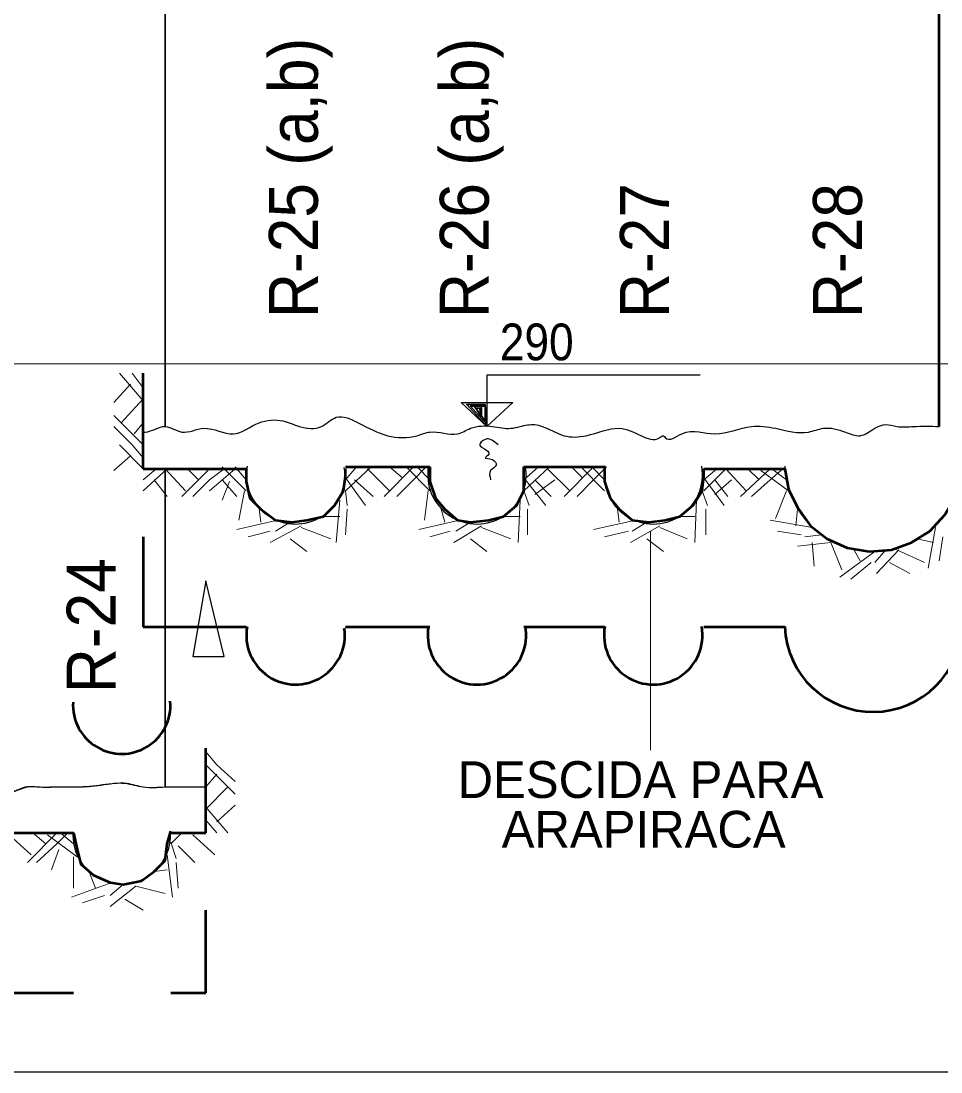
# Model space of a CAD drawing. Extents: x 8426.2 to 8495.4, y 19933.5 to 19963.2.
# Drawn here: x 8473.14 to 8478.14, y 19944.82 to 19950.53 of the extents above; entities that cross this region are included whole.
import ezdxf

# ---------------------------------------------------------------- set-up
doc = ezdxf.new("R2010")
doc.units = 0
doc.header["$LTSCALE"] = 0.11
for name, color, linetype, lineweight in [('1', 7, 'Continuous', 35), ('2', 7, 'Continuous', 13), ('3', 7, 'Continuous', 25), ('4', 7, 'Continuous', 25)]:
    doc.layers.add(name, color=color, linetype=linetype, lineweight=lineweight)

msp = doc.modelspace()

# ---------------------------------------------------------------- linework, layer by layer
at = {"layer": '1'}
msp.add_line((8473.92, 19948.33), (8473.92, 19955.82), dxfattribs=at)
at = {"layer": '1', "lineweight": 25}
msp.add_lwpolyline([(8476.83, 19948.61), (8475.67, 19948.61), (8475.67, 19948.33), (8475.53, 19948.46), (8475.81, 19948.46), (8475.67, 19948.33)], dxfattribs=at)
at = {"layer": '1'}
for points in [[(8475.67, 19948.33), (8475.56, 19948.45), (8475.66, 19948.45), (8475.67, 19948.34), (8475.58, 19948.44), (8475.66, 19948.44), (8475.66, 19948.36), (8475.6, 19948.44), (8475.64, 19948.44), (8475.64, 19948.39), (8475.63, 19948.43)], [(8475.64, 19948.4), (8475.64, 19948.43), (8475.61, 19948.43), (8475.64, 19948.38)], [(8473.92, 19946.37), (8473.92, 19947.42), (8473.92, 19948.1)]]:
    msp.add_lwpolyline(points, dxfattribs=at)
at = {"layer": '1', "lineweight": 25}
msp.add_spline([(8475.73, 19948.23), (8475.66, 19948.26), (8475.63, 19948.23), (8475.67, 19948.2), (8475.68, 19948.18), (8475.66, 19948.16), (8475.7, 19948.15), (8475.72, 19948.12), (8475.69, 19948.09), (8475.69, 19948.04)], degree=3, dxfattribs=at)
at = {"layer": '2', "lineweight": 53}
for p, q in [((8478.13, 19948.33), (8478.13, 19954.72)), ((8473.8, 19948.1), (8473.8, 19948.62)), ((8473.8, 19948.1), (8474.36, 19948.1)), ((8474.9, 19948.11), (8475.36, 19948.11)), ((8475.87, 19948.11), (8476.31, 19948.11)), ((8476.85, 19948.1), (8477.29, 19948.1)), ((8473.8, 19947.73), (8473.8, 19947.24)), ((8473.8, 19947.24), (8474.36, 19947.24)), ((8474.9, 19947.24), (8475.36, 19947.24)), ((8475.87, 19947.24), (8476.31, 19947.24)), ((8476.85, 19947.24), (8477.29, 19947.24)), ((8474.14, 19946.12), (8474.14, 19946.58)), ((8472.95, 19946.12), (8473.42, 19946.12)), ((8473.95, 19946.12), (8474.14, 19946.12)), ((8474.14, 19945.25), (8474.14, 19945.7)), ((8472.95, 19945.25), (8473.42, 19945.25)), ((8473.95, 19945.25), (8474.14, 19945.25))]:
    msp.add_line(p, q, dxfattribs=at)
at = {"layer": '2'}
for p, q in [((8473.8, 19948.47), (8473.67, 19948.62)), ((8473.8, 19948.54), (8473.74, 19948.62)), ((8473.73, 19948.56), (8473.64, 19948.46)), ((8473.8, 19948.48), (8473.68, 19948.35)), ((8473.8, 19948.23), (8473.64, 19948.39)), ((8473.74, 19948.23), (8473.64, 19948.33)), ((8473.8, 19948.35), (8473.75, 19948.29)), ((8473.8, 19948.1), (8473.67, 19948.23)), ((8473.8, 19948.16), (8473.74, 19948.23)), ((8473.73, 19948.17), (8473.64, 19948.09)), ((8473.87, 19948.1), (8473.8, 19948.04)), ((8473.93, 19948.1), (8473.8, 19947.98)), ((8473.92, 19948.1), (8474.03, 19947.98)), ((8474.16, 19948.1), (8474.01, 19947.95)), ((8474.04, 19948.1), (8474.1, 19948.04)), ((8474.24, 19948.1), (8474.16, 19948.04)), ((8474.3, 19948.1), (8474.16, 19947.98)), ((8474.36, 19947.98), (8474.23, 19948.11)), ((8474.36, 19948.04), (8474.3, 19948.11)), ((8474.96, 19948.11), (8474.9, 19948.04)), ((8475.04, 19948.11), (8474.9, 19947.98)), ((8475.02, 19948.1), (8475.14, 19947.98)), ((8475.27, 19948.11), (8475.11, 19947.95)), ((8475.14, 19948.11), (8475.21, 19948.05)), ((8475.36, 19947.98), (8475.23, 19948.11)), ((8475.34, 19948.11), (8475.27, 19948.04)), ((8475.36, 19948.04), (8475.29, 19948.11)), ((8475.95, 19948.11), (8475.87, 19948.04)), ((8476.01, 19948.11), (8475.87, 19947.98)), ((8476, 19948.1), (8476.12, 19947.98)), ((8476.25, 19948.11), (8476.09, 19947.95)), ((8476.13, 19948.11), (8476.19, 19948.05)), ((8476.31, 19947.98), (8476.18, 19948.11)), ((8476.31, 19948.04), (8476.24, 19948.11)), ((8476.32, 19948.11), (8476.25, 19948.04)), ((8476.92, 19948.1), (8476.85, 19948.04)), ((8476.97, 19948.1), (8476.85, 19947.98)), ((8476.97, 19948.1), (8477.08, 19947.98)), ((8477.21, 19948.1), (8477.05, 19947.95)), ((8477.09, 19948.1), (8477.15, 19948.04)), ((8477.31, 19947.98), (8477.16, 19948.09)), ((8477.28, 19948.1), (8477.21, 19948.04)), ((8477.3, 19948.04), (8477.22, 19948.1)), ((8473.86, 19948.04), (8473.93, 19947.95)), ((8474.16, 19948.04), (8474.07, 19947.95)), ((8474.23, 19948.04), (8474.31, 19947.95)), ((8474.27, 19948.03), (8474.23, 19947.93)), ((8474.9, 19948.05), (8475.01, 19947.9)), ((8474.95, 19948.04), (8475.05, 19947.95)), ((8475.27, 19948.04), (8475.18, 19947.95)), ((8475.87, 19948.05), (8475.99, 19947.9)), ((8475.93, 19948.04), (8476.02, 19947.95)), ((8475.93, 19947.96), (8476.04, 19948.04)), ((8476.25, 19948.04), (8476.16, 19947.95)), ((8476.85, 19948.05), (8476.96, 19947.9)), ((8476.91, 19948.04), (8476.98, 19947.95)), ((8476.91, 19947.96), (8477, 19948.04)), ((8477.21, 19948.04), (8477.11, 19947.95)), ((8474.35, 19947.98), (8474.32, 19947.82)), ((8474.9, 19947.98), (8474.91, 19947.9)), ((8475.35, 19947.98), (8475.33, 19947.82)), ((8475.87, 19947.98), (8475.9, 19947.9)), ((8476.84, 19947.98), (8476.87, 19947.9)), ((8477.3, 19947.98), (8477.24, 19947.83)), ((8474.87, 19947.93), (8474.85, 19947.7)), ((8475.85, 19947.93), (8475.84, 19947.7)), ((8476.81, 19947.93), (8476.8, 19947.7)), ((8474.43, 19947.88), (8474.44, 19947.81)), ((8474.91, 19947.88), (8474.9, 19947.74)), ((8475.42, 19947.88), (8475.44, 19947.81)), ((8475.89, 19947.88), (8475.89, 19947.74)), ((8476.38, 19947.88), (8476.39, 19947.81)), ((8476.86, 19947.88), (8476.86, 19947.74)), ((8477.36, 19947.88), (8477.35, 19947.79)), ((8474.53, 19947.82), (8474.31, 19947.77)), ((8474.6, 19947.81), (8474.52, 19947.76)), ((8474.78, 19947.84), (8474.87, 19947.84)), ((8475.52, 19947.82), (8475.3, 19947.77)), ((8475.58, 19947.81), (8475.5, 19947.76)), ((8475.76, 19947.84), (8475.85, 19947.84)), ((8476.48, 19947.82), (8476.25, 19947.77)), ((8476.54, 19947.81), (8476.46, 19947.76)), ((8476.72, 19947.84), (8476.8, 19947.84)), ((8477.44, 19947.78), (8477.21, 19947.82)), ((8474.49, 19947.76), (8474.37, 19947.73)), ((8474.66, 19947.79), (8474.49, 19947.7)), ((8474.66, 19947.78), (8474.82, 19947.72)), ((8475.47, 19947.76), (8475.36, 19947.73)), ((8475.64, 19947.79), (8475.49, 19947.7)), ((8475.64, 19947.78), (8475.8, 19947.72)), ((8476.44, 19947.76), (8476.31, 19947.73)), ((8476.61, 19947.79), (8476.45, 19947.7)), ((8476.61, 19947.78), (8476.76, 19947.72)), ((8477.38, 19947.74), (8477.25, 19947.76)), ((8478.11, 19947.78), (8478.07, 19947.56)), ((8474.6, 19947.72), (8474.69, 19947.65)), ((8475.58, 19947.72), (8475.67, 19947.65)), ((8476.54, 19947.72), (8476.63, 19947.65)), ((8477.54, 19947.7), (8477.36, 19947.68)), ((8477.49, 19947.74), (8477.4, 19947.73)), ((8477.44, 19947.7), (8477.45, 19947.57)), ((8477.54, 19947.7), (8477.6, 19947.55)), ((8478.01, 19947.72), (8478.1, 19947.7)), ((8478.15, 19947.73), (8478.13, 19947.6)), ((8477.78, 19947.65), (8477.59, 19947.51)), ((8477.66, 19947.67), (8477.7, 19947.6)), ((8477.84, 19947.66), (8477.78, 19947.59)), ((8477.91, 19947.66), (8477.79, 19947.53)), ((8477.9, 19947.66), (8478.05, 19947.59)), ((8477.76, 19947.59), (8477.65, 19947.5)), ((8477.86, 19947.59), (8477.97, 19947.53)), ((8474.14, 19946.56), (8474.2, 19946.49)), ((8474.14, 19946.49), (8474.3, 19946.33)), ((8474.2, 19946.49), (8474.3, 19946.4)), ((8474.14, 19946.37), (8474.2, 19946.44)), ((8474.14, 19946.25), (8474.26, 19946.37)), ((8474.14, 19946.26), (8474.26, 19946.12)), ((8474.2, 19946.18), (8474.3, 19946.27)), ((8474.14, 19946.19), (8474.2, 19946.12)), ((8473.07, 19946.11), (8473.19, 19946)), ((8473.33, 19946.12), (8473.17, 19945.96)), ((8473.2, 19946.12), (8473.27, 19946.06)), ((8473.44, 19945.99), (8473.28, 19946.11)), ((8473.39, 19946.12), (8473.33, 19946.06)), ((8473.42, 19946.06), (8473.35, 19946.12)), ((8474.01, 19946.12), (8473.95, 19946.06)), ((8474.07, 19946.11), (8474.19, 19946)), ((8473.33, 19946.06), (8473.22, 19945.96)), ((8473.34, 19946.03), (8473.3, 19945.92)), ((8473.95, 19946.07), (8473.98, 19945.98)), ((8473.99, 19946.05), (8474.08, 19945.96)), ((8473.42, 19945.99), (8473.42, 19945.82)), ((8473.93, 19946), (8473.96, 19945.77)), ((8473.86, 19945.91), (8473.93, 19945.92)), ((8473.98, 19945.96), (8473.99, 19945.82)), ((8473.51, 19945.9), (8473.54, 19945.82)), ((8473.63, 19945.85), (8473.41, 19945.77)), ((8473.69, 19945.84), (8473.62, 19945.78)), ((8473.76, 19945.83), (8473.62, 19945.72)), ((8473.76, 19945.83), (8473.92, 19945.79)), ((8473.59, 19945.78), (8473.47, 19945.74)), ((8473.7, 19945.76), (8473.8, 19945.7))]:
    msp.add_line(p, q, dxfattribs=at)
at = {"layer": '2', "lineweight": 35}
msp.add_line((8473.8, 19948.62), (8473.8, 19948.1), dxfattribs=at)
at = {"layer": '2', "lineweight": 25}
msp.add_line((8474.14, 19946.12), (8474.14, 19946.58), dxfattribs=at)
at = {"layer": '2', "lineweight": 53}
for points in [[(8474.36, 19948.1), (8474.36, 19948.03), (8474.38, 19947.94), (8474.44, 19947.88), (8474.52, 19947.82), (8474.61, 19947.81), (8474.69, 19947.82), (8474.78, 19947.84), (8474.84, 19947.9), (8474.89, 19947.98), (8474.9, 19948.06), (8474.9, 19948.1)], [(8475.36, 19948.11), (8475.36, 19948.03), (8475.39, 19947.94), (8475.44, 19947.88), (8475.51, 19947.82), (8475.58, 19947.81), (8475.68, 19947.82), (8475.76, 19947.84), (8475.83, 19947.9), (8475.87, 19947.98), (8475.87, 19948.06), (8475.87, 19948.11)], [(8476.31, 19948.11), (8476.31, 19948.03), (8476.34, 19947.94), (8476.39, 19947.88), (8476.46, 19947.82), (8476.55, 19947.81), (8476.64, 19947.82), (8476.72, 19947.84), (8476.79, 19947.9), (8476.84, 19947.98), (8476.85, 19948.06), (8476.85, 19948.1)], [(8477.29, 19948.1), (8477.31, 19947.99), (8477.36, 19947.89), (8477.43, 19947.79), (8477.52, 19947.72), (8477.63, 19947.67), (8477.75, 19947.65), (8477.87, 19947.66), (8477.98, 19947.7), (8478.08, 19947.76), (8478.16, 19947.85), (8478.22, 19947.95), (8478.25, 19948.06), (8478.25, 19948.11)], [(8473.42, 19946.12), (8473.44, 19946.03), (8473.46, 19945.95), (8473.53, 19945.89), (8473.62, 19945.85), (8473.69, 19945.84), (8473.79, 19945.86), (8473.86, 19945.91), (8473.92, 19945.97), (8473.93, 19946.06), (8473.95, 19946.13)]]:
    msp.add_lwpolyline(points, dxfattribs=at)
at = {"layer": '2', "lineweight": 25}
msp.add_lwpolyline([(8474.14, 19947.49), (8474.07, 19947.08), (8474.24, 19947.08)], close=True, dxfattribs=at)
at = {"layer": '2', "lineweight": 53}
for centre, radius, start, end in [((8474.6288, 19947.1949), 0.268, 169.8463, 8.4206), ((8475.6155, 19947.1949), 0.268, 169.5566, 10.4434), ((8476.5748, 19947.1949), 0.268, 169.5566, 10.1537), ((8477.7712, 19947.2595), 0.4815, 182.0654, 359.0456), ((8473.6828, 19946.815), 0.2652, 176.5407, 4.4698), ((8473.6828, 19946.815), 0.2652, 176.5407, 4.4698), ((8473.6828, 19946.815), 0.2652, 176.5407, 4.4698)]:
    msp.add_arc(centre, radius, start, end, dxfattribs=at)
at = {"layer": '3', "lineweight": 13}
msp.add_line((8431.27, 19948.67), (8493.73, 19948.67), dxfattribs=at)
at = {"layer": '3'}
for p, q in [((8475.36, 19948.11), (8474.9, 19948.11)), ((8476.31, 19948.11), (8475.87, 19948.11)), ((8477.29, 19948.1), (8476.85, 19948.1)), ((8473.42, 19946.12), (8472.95, 19946.12)), ((8474.14, 19946.12), (8473.95, 19946.12)), ((8431.27, 19944.82), (8493.73, 19944.82))]:
    msp.add_line(p, q, dxfattribs=at)
msp.add_lwpolyline([(8474.36, 19948.1), (8473.8, 19948.1), (8473.8, 19948.3)], dxfattribs=at)
for centre, radius, start, end in [((8474.6288, 19948.0676), 0.268, 169.8463, 8.4206), ((8475.6155, 19948.0676), 0.268, 169.5566, 10.4434), ((8476.5748, 19948.0676), 0.268, 169.5566, 10.1537), ((8477.7712, 19948.1322), 0.4815, 182.0654, 359.0456), ((8473.6828, 19946.1068), 0.2652, 176.5407, 4.4698)]:
    msp.add_arc(centre, radius, start, end, dxfattribs=at)
for points in [[(8473.8, 19948.3), (8473.81, 19948.3), (8473.92, 19948.33), (8474.01, 19948.3), (8474.13, 19948.32), (8474.29, 19948.29), (8474.43, 19948.35), (8474.56, 19948.36), (8474.65, 19948.33), (8474.77, 19948.33), (8474.85, 19948.38), (8474.97, 19948.35), (8475.13, 19948.28), (8475.29, 19948.28), (8475.36, 19948.3), (8475.51, 19948.29), (8475.58, 19948.32), (8475.7, 19948.33), (8475.8, 19948.32), (8475.85, 19948.33), (8475.93, 19948.34), (8476.09, 19948.28), (8476.21, 19948.28), (8476.39, 19948.32), (8476.51, 19948.28), (8476.61, 19948.27), (8476.63, 19948.28), (8476.64, 19948.27), (8476.73, 19948.29), (8476.91, 19948.29), (8477.11, 19948.33), (8477.24, 19948.32), (8477.42, 19948.3), (8477.5, 19948.32), (8477.62, 19948.3), (8477.7, 19948.28), (8477.78, 19948.32), (8477.84, 19948.34), (8477.9, 19948.33), (8477.99, 19948.33), (8478.13, 19948.33)], [(8473.8, 19948.3), (8473.81, 19948.3), (8473.92, 19948.33), (8474.01, 19948.3), (8474.13, 19948.32), (8474.29, 19948.29), (8474.43, 19948.35), (8474.56, 19948.36), (8474.65, 19948.33), (8474.77, 19948.33), (8474.85, 19948.38), (8474.97, 19948.35), (8475.13, 19948.28), (8475.29, 19948.28), (8475.36, 19948.3), (8475.51, 19948.29), (8475.58, 19948.32), (8475.7, 19948.33), (8475.8, 19948.32), (8475.85, 19948.33), (8475.93, 19948.34), (8476.09, 19948.28), (8476.21, 19948.28), (8476.39, 19948.32), (8476.51, 19948.28), (8476.61, 19948.27), (8476.63, 19948.28), (8476.64, 19948.27), (8476.73, 19948.29), (8476.91, 19948.29), (8477.11, 19948.33), (8477.24, 19948.32), (8477.42, 19948.3), (8477.5, 19948.32), (8477.62, 19948.3), (8477.7, 19948.28), (8477.78, 19948.32), (8477.84, 19948.34), (8477.9, 19948.33), (8477.99, 19948.33), (8478.13, 19948.33)], [(8473.8, 19948.3), (8473.81, 19948.3), (8473.92, 19948.33), (8474.01, 19948.3), (8474.13, 19948.32), (8474.29, 19948.29), (8474.43, 19948.35), (8474.56, 19948.36), (8474.65, 19948.33), (8474.77, 19948.33), (8474.85, 19948.38), (8474.97, 19948.35), (8475.13, 19948.28), (8475.29, 19948.28), (8475.36, 19948.3), (8475.51, 19948.29), (8475.58, 19948.32), (8475.7, 19948.33), (8475.8, 19948.32), (8475.85, 19948.33), (8475.93, 19948.34), (8476.09, 19948.28), (8476.21, 19948.28), (8476.39, 19948.32), (8476.51, 19948.28), (8476.61, 19948.27), (8476.63, 19948.28), (8476.64, 19948.27), (8476.73, 19948.29), (8476.91, 19948.29), (8477.11, 19948.33), (8477.24, 19948.32), (8477.42, 19948.3), (8477.5, 19948.32), (8477.62, 19948.3), (8477.7, 19948.28), (8477.78, 19948.32), (8477.84, 19948.34), (8477.9, 19948.33), (8477.99, 19948.33), (8478.13, 19948.33)], [(8473.8, 19948.3), (8473.81, 19948.3), (8473.92, 19948.33), (8474.01, 19948.3), (8474.13, 19948.32), (8474.29, 19948.29), (8474.43, 19948.35), (8474.56, 19948.36), (8474.65, 19948.33), (8474.77, 19948.33), (8474.85, 19948.38), (8474.97, 19948.35), (8475.13, 19948.28), (8475.29, 19948.28), (8475.36, 19948.3), (8475.51, 19948.29), (8475.58, 19948.32), (8475.7, 19948.33), (8475.8, 19948.32), (8475.85, 19948.33), (8475.93, 19948.34), (8476.09, 19948.28), (8476.21, 19948.28), (8476.39, 19948.32), (8476.51, 19948.28), (8476.61, 19948.27), (8476.63, 19948.28), (8476.64, 19948.27), (8476.73, 19948.29), (8476.91, 19948.29), (8477.11, 19948.33), (8477.24, 19948.32), (8477.42, 19948.3), (8477.5, 19948.32), (8477.62, 19948.3), (8477.7, 19948.28), (8477.78, 19948.32), (8477.84, 19948.34), (8477.9, 19948.33), (8477.99, 19948.33), (8478.13, 19948.33)], [(8466.81, 19946.36), (8466.93, 19946.35), (8467.1, 19946.31), (8467.24, 19946.34), (8467.4, 19946.31), (8467.52, 19946.36), (8467.62, 19946.38), (8467.69, 19946.35), (8467.86, 19946.39), (8467.92, 19946.36), (8468.03, 19946.35), (8468.19, 19946.36), (8468.31, 19946.34), (8468.44, 19946.36), (8468.56, 19946.35), (8468.65, 19946.38), (8468.94, 19946.37), (8469.06, 19946.37), (8469.22, 19946.36), (8469.3, 19946.37), (8469.41, 19946.38), (8469.47, 19946.36), (8469.61, 19946.38), (8469.71, 19946.37), (8469.79, 19946.35), (8469.91, 19946.38), (8469.98, 19946.39), (8470.08, 19946.4), (8470.13, 19946.38), (8470.32, 19946.4), (8470.43, 19946.34), (8470.53, 19946.37), (8470.6, 19946.38), (8470.69, 19946.37), (8470.85, 19946.35), (8470.99, 19946.37), (8471.08, 19946.37), (8471.16, 19946.34), (8471.49, 19946.35), (8471.55, 19946.36), (8471.68, 19946.37), (8471.84, 19946.39), (8471.96, 19946.35), (8472.08, 19946.38), (8472.25, 19946.36), (8472.36, 19946.39), (8472.44, 19946.4), (8472.64, 19946.39), (8472.73, 19946.36), (8472.88, 19946.35), (8472.99, 19946.35), (8473.07, 19946.34), (8473.17, 19946.37), (8473.24, 19946.37), (8473.33, 19946.37), (8473.44, 19946.37), (8473.57, 19946.38), (8473.71, 19946.39), (8473.8, 19946.37), (8473.92, 19946.37), (8474.03, 19946.37), (8474.1, 19946.37), (8474.14, 19946.37)], [(8466.81, 19946.36), (8466.91, 19946.35), (8467.1, 19946.31), (8467.24, 19946.34), (8467.4, 19946.31), (8467.52, 19946.36), (8467.6, 19946.38), (8467.69, 19946.35), (8467.85, 19946.39), (8467.91, 19946.36), (8468.03, 19946.35), (8468.18, 19946.36), (8468.3, 19946.34), (8468.43, 19946.36), (8468.56, 19946.35), (8468.65, 19946.38), (8468.93, 19946.37), (8469.06, 19946.37), (8469.2, 19946.36), (8469.29, 19946.37), (8469.4, 19946.38), (8469.47, 19946.36), (8469.61, 19946.38), (8469.7, 19946.37), (8469.78, 19946.35), (8469.91, 19946.38), (8469.97, 19946.39), (8470.07, 19946.4), (8470.13, 19946.38), (8470.31, 19946.4), (8470.42, 19946.34), (8470.53, 19946.37), (8470.59, 19946.38), (8470.68, 19946.37), (8470.84, 19946.35), (8470.98, 19946.37), (8471.07, 19946.37), (8471.15, 19946.34), (8471.48, 19946.35), (8471.54, 19946.36), (8471.67, 19946.37), (8471.84, 19946.39), (8471.96, 19946.35), (8472.08, 19946.38), (8472.25, 19946.36), (8472.34, 19946.39), (8472.44, 19946.4), (8472.64, 19946.39), (8472.72, 19946.36), (8472.88, 19946.35), (8472.99, 19946.35), (8473.07, 19946.34), (8473.16, 19946.37), (8473.24, 19946.37), (8473.31, 19946.37), (8473.42, 19946.37), (8473.56, 19946.38), (8473.7, 19946.39), (8473.8, 19946.37), (8473.92, 19946.37), (8474.03, 19946.37), (8474.1, 19946.37), (8474.13, 19946.37)]]:
    msp.add_spline(points, degree=3, dxfattribs=at)
at = {"layer": '4', "lineweight": 13}
msp.add_line((8476.56, 19946.57), (8476.56, 19947.76), dxfattribs=at)

# ---------------------------------------------------------------- texts
at = {"layer": '1', "width": 0.95}
for s, p in [('R-25 (a,b)', (8474.75, 19948.92)), ('R-26 (a,b)', (8475.68, 19948.92)), ('R-27', (8476.66, 19948.92)), ('R-28', (8477.71, 19948.92)), ('R-24', (8473.65, 19946.88))]:
    msp.add_text(s, height=0.2665, rotation=90, dxfattribs=at).set_placement(p)
at = {"layer": '2', "width": 0.9}
msp.add_text('290', height=0.1999, dxfattribs=at).set_placement((8475.74, 19948.69))
at = {"layer": '2'}
for s, p in [('DESCIDA PARA', (8475.51, 19946.31)), ('ARAPIRACA', (8475.75, 19946.04))]:
    msp.add_text(s, height=0.1999, dxfattribs=at).set_placement(p)

doc.saveas('drawing.dxf')
